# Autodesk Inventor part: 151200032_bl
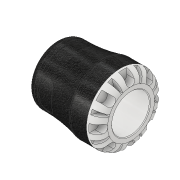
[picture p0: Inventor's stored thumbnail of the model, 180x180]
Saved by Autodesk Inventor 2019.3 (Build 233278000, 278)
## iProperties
Created: 2016-12
Part Number: 151200032_bl
Material: PVC-Piping
Description: PLASSON G-PLASS END CAP 32
Document SubType Name: Modeling
Designer: KIM
Mass: 57.8335 g
Surface Area: 121.129 cm^2
Volume: 41.3096 cm^3
Density: 1.4 g/cm^3
Appearance: Black Cast
Author: KIM
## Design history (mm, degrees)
derived "151200.ipt"
feature "Solid1::151200.ipt" dims "ScaleForDerivedMember" = 10
tag "TaggingFeature1"
body "Solid1"
other parameters: "d1" = 23.1 [user parameter], "d2" = 32 [user parameter], "d4" = 58 [user parameter], "d6" = 55 [user parameter], "d7" = 60.5 [user parameter], "d8" = 49.3 [user parameter], "d13" = 7.2 [user parameter], "d14" = 7.2 [user parameter], "d15" = 0 [user parameter], "d17" = 360 deg [user parameter], "d19" = 8 deg [user parameter], "d20" = 0.64 [user parameter], "d21" = 0.64 [user parameter], "d22" = 8 deg [user parameter], "d24" = 0 [user parameter], "d26" = 360 deg [user parameter], "d32" = 5.8 [user parameter], "d33" = 5.8 [user parameter], "d34" = 7.04 [user parameter], "d35" = 11.2 [user parameter], "d36" = 14.112 [user parameter], "d37" = 0 [user parameter], "d42" = 360 deg [user parameter], "d45" = 9.52 [user parameter], "d46" = 0.64 [user parameter], "d48" = 0 [user parameter], "d49" = 0.58 [user parameter], "d_" = 32 [user parameter], "E_" = 58 [user parameter], "l_" = 55 [user parameter], "d9" = 9 [user parameter], "d11" = 58 [user parameter]
